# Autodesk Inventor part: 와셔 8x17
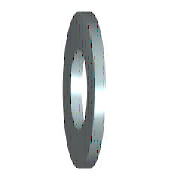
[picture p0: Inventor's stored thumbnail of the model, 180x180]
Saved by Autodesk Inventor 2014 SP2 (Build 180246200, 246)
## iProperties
Created: 2012-02
Part Number: 와셔 8x17
Material: 강철, 연강
Description: 평면 와셔
Document SubType Name: Modeling
Standard: KS B 1326
Designer: mduedu
Standards Organization: KS
Language: ko-KR
Size Designation: 8x17
Categories: <MemberInstance><Categories><Category DisplayName="조임쇠" InternalName="e4da775c-781d-43d5-af7c-5136215cf5a6" Mnemonic="FSTN"><Category DisplayName="와셔" InternalN
Density: 7.86 g/cm^3
Appearance: 파란색 - 벽 페인트 - 광택
Mass: 2.05445 g
Surface Area: 4.57416 cm^2
Volume: 0.261381 cm^3
IsCustomPart: 1
Author: mduedu
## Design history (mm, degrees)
sketch "스케치"
  geometry: C1 r 8.5 at (0, 0); C2 r 4.5 at (0, 0); 1 further point
  constraints: 2 centre point, 2 coincident
  dimensions: "d0" = 9 diameter of C2 (= SD1); "d1" = 17 diameter of C1 (= SD2)
extrude "본체" new body sketch "스케치" distance "d2" = 1.6 (= SD); taper "d3" = 0 deg
workaxis "Work Axis1"
workplane "Work Plane1"
body "Solid1"
other parameters: "SD1" = 9 [user parameter; used in 1 equation term], "SD2" = 17 [user parameter; used in 1 equation term], "SD" = 1.6 [user parameter; used in 1 equation term], "d4" = 0, "d5" = 0, "d6" = 0, "d7" = 0, "NND" = 8 [user parameter]
